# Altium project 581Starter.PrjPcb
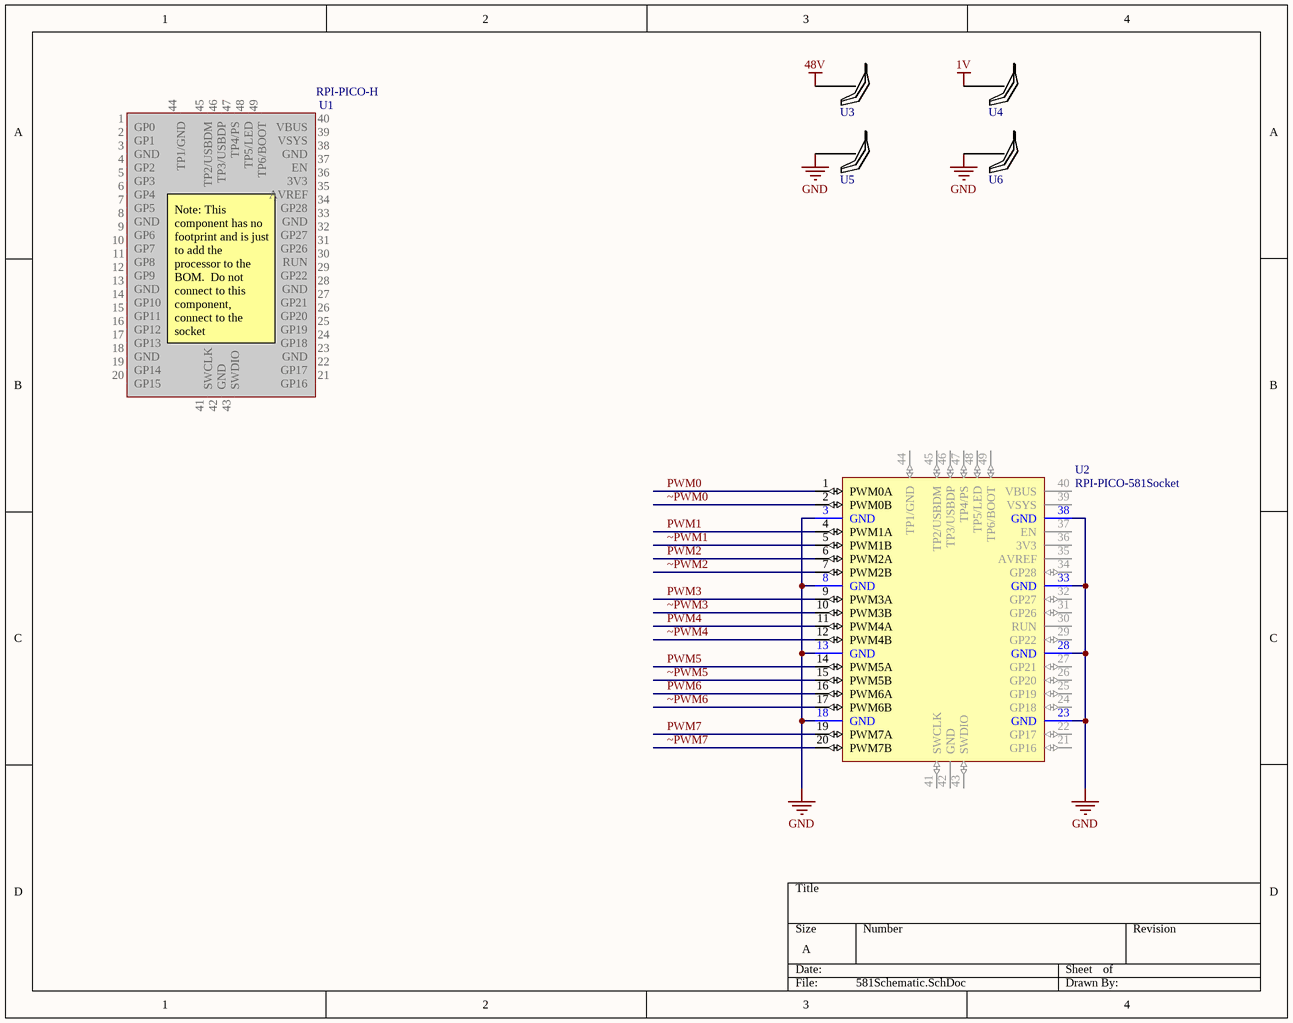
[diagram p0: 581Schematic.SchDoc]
1 sheet, 6 parts. Net scope: global (net labels, ports and power ports of the same name join across sheets).
Board file: 581PCB.PcbDoc

## Sheet 581Schematic.SchDoc
size A; SheetNumber: 1; SheetTotal: 1

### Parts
U1  RPI-PICO-H
U2  RPI-PICO-581Socket  [RPI-PICO-MOD]
U3  Banana Jack  [Banana Jack]  (value not drawn)
U4  Banana Jack  [Banana Jack]  (value not drawn)
U5  Banana Jack  [Banana Jack]  (value not drawn)
U6  Banana Jack  [Banana Jack]  (value not drawn)

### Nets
1V: U4.1
48V: U3.1
GND: U2.3(GND) U2.8(GND) U2.13(GND) U2.18(GND) U2.23(GND) U2.28(GND) U2.33(GND) U2.38(GND) U5.1 U6.1
PWM0: U2.1(PWM0A)
PWM1: U2.4(PWM1A)
PWM2: U2.6(PWM2A)
PWM3: U2.9(PWM3A)
PWM4: U2.11(PWM4A)
PWM5: U2.14(PWM5A)
PWM6: U2.16(PWM6A)
PWM7: U2.19(PWM7A)
~PWM0: U2.2(PWM0B)
~PWM1: U2.5(PWM1B)
~PWM2: U2.7(PWM2B)
~PWM3: U2.10(PWM3B)
~PWM4: U2.12(PWM4B)
~PWM5: U2.15(PWM5B)
~PWM6: U2.17(PWM6B)
~PWM7: U2.20(PWM7B)

Not connected (* = marked no-connect by the designer): U1 1(GP0) 2(GP1) 3(GND) 4(GP2) 5(GP3) 6(GP4) 7(GP5) 8(GND) 9(GP6) 10(GP7) 11(GP8) 12(GP9) 13(GND) 14(GP10) 15(GP11) 16(GP12) 17(GP13) 18(GND) 19(GP14) 20(GP15) 21(GP16) 22(GP17) 23(GND) 24(GP18) 25(GP19) 26(GP20) 27(GP21) 28(GND) 29(GP22) 30(RUN) 31(GP26) 32(GP27) 33(GND) 34(GP28) 35(AVREF) 36(3V3) 37(EN) 38(GND) 39(VSYS) 40(VBUS) 41(SWCLK) 42(GND) 43(SWDIO) 44(TP1/GND) 45(TP2/USBDM) 46(TP3/USBDP) 47(TP4/PS) 48(TP5/LED) 49(TP6/BOOT); U2 21(GP16) 22(GP17) 24(GP18) 25(GP19) 26(GP20) 27(GP21) 29(GP22) 30(RUN) 31(GP26) 32(GP27) 34(GP28) 35(AVREF) 36(3V3) 37(EN) 39(VSYS) 40(VBUS) 41(SWCLK) 42(GND) 43(SWDIO) 44(TP1/GND) 45(TP2/USBDM) 46(TP3/USBDP) 47(TP4/PS) 48(TP5/LED) 49(TP6/BOOT)

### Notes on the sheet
- (near U1) Note: This component has no footprint and is just to add the processor to the BOM.  Do not connect to this component, connect to the socket

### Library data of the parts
U1 = RPI-PICO-H: RASPBERRY PI PICO HRP2040 BOARD; Manufacturer: Raspberry Pi Foundation; Manufacturer Part No: SC0915
U2 = RPI-PICO-581Socket: RASPBERRY PI PICO RP2040 BOARD; Manufacturer: Raspberry Pi Foundation; Manufacturer Part No: SC0915
U3-U6 = Banana Jack: 575-8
